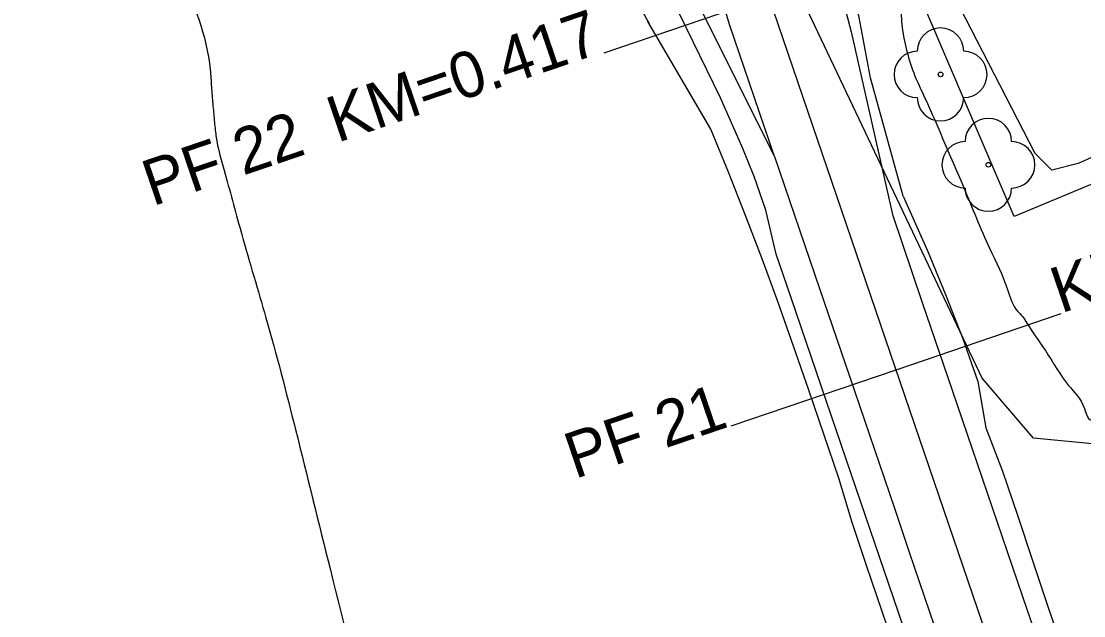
# Model space of a CAD drawing. Extents: x -478102 to -473059, y -1117705 to -1114104.
# Drawn here: x -476531.57 to -476485.84, y -1116863.12 to -1116837.52 of the extents above; entities that cross this region are included whole.
import ezdxf

# ---------------------------------------------------------------- set-up
doc = ezdxf.new("R2010")
doc.units = 0
for name, color, linetype in [('cesty', 7, 'Continuous'), ('ObPÚ', 7, 'Continuous'), ('POLYGONY_SITUACE_PF', 7, 'Continuous'), ('POLYGONY_SITUACE_PF_POPISY', 7, 'Continuous'), ('POLYGONY_SITUACE_PO', 7, 'Continuous'), ('RozhraniKultur', 7, 'Continuous'), ('RozhraniVozovky', 7, 'Continuous'), ('Vrstevnice_hlavni', 7, 'Continuous'), ('Vrstevnice_vedlejsi', 7, 'Continuous'), ('ZnackyStromu', 7, 'Continuous')]:
    doc.layers.add(name, color=color, linetype=linetype)

msp = doc.modelspace()

# ---------------------------------------------------------------- linework, layer by layer
msp.add_line((-476504.565, -1116837.587), (-476505.152, -1116836.498))
msp.add_lwpolyline([(-476493.611, -1116845.046), (-476495.024, -1116839.954), (-476495.915, -1116835.202), (-476496.059, -1116834.438), (-476495.701, -1116828.922), (-476495.475, -1116827.69)])
at = {"layer": 'cesty'}
for p, q in [((-476502.931, -1116835.794), (-476499.157, -1116843.34)), ((-476496.354, -1116836.065), (-476495.859, -1116837.974)), ((-476501.886, -1116842.158), (-476504.604, -1116837.532)), ((-476504.604, -1116837.532), (-476504.565, -1116837.587)), ((-476501.482, -1116840.818), (-476503.246, -1116837.201)), ((-476504.565, -1116837.587), (-476504.553, -1116837.573)), ((-476495.859, -1116837.974), (-476495.859, -1116837.974)), ((-476495.859, -1116837.974), (-476495.859, -1116837.974)), ((-476495.859, -1116837.974), (-476495.859, -1116837.974)), ((-476495.859, -1116837.974), (-476494.08, -1116845.836)), ((-476500.509, -1116843), (-476501.482, -1116840.818)), ((-476501.132, -1116844.013), (-476501.886, -1116842.158)), ((-476500.03, -1116844.197), (-476500.509, -1116843)), ((-476500.402, -1116845.878), (-476501.132, -1116844.013)), ((-476499.527, -1116845.646), (-476500.03, -1116844.197)), ((-476499.076, -1116847.539), (-476499.527, -1116845.646)), ((-476499.69, -1116847.748), (-476500.402, -1116845.878)), ((-476494.08, -1116845.836), (-476492.79, -1116849.622)), ((-476498.43, -1116849.432), (-476499.076, -1116847.539)), ((-476498.997, -1116849.625), (-476499.69, -1116847.748)), ((-476497.785, -1116851.325), (-476498.43, -1116849.432)), ((-476498.334, -1116851.512), (-476498.997, -1116849.625)), ((-476492.79, -1116849.622), (-476491.499, -1116853.408)), ((-476497.68, -1116853.402), (-476498.334, -1116851.512)), ((-476495.849, -1116857.004), (-476497.785, -1116851.325)), ((-476497.031, -1116855.294), (-476497.68, -1116853.402)), ((-476491.499, -1116853.408), (-476490.208, -1116857.194)), ((-476496.382, -1116857.185), (-476497.031, -1116855.294)), ((-476495.805, -1116859.102), (-476496.382, -1116857.185)), ((-476493.268, -1116864.576), (-476495.849, -1116857.004)), ((-476490.208, -1116857.194), (-476489.563, -1116859.087)), ((-476495.173, -1116860.999), (-476495.805, -1116859.102)), ((-476489.563, -1116859.087), (-476488.918, -1116860.98)), ((-476494.532, -1116862.894), (-476495.173, -1116860.999)), ((-476488.918, -1116860.98), (-476488.272, -1116862.873)), ((-476493.891, -1116864.788), (-476494.532, -1116862.894)), ((-476488.272, -1116862.873), (-476487.627, -1116864.766))]:
    msp.add_line(p, q, dxfattribs=at)
for points in [[(-476501.093, -1116837.661), (-476501.723, -1116835.529)], [(-476500.448, -1116839.554), (-476501.093, -1116837.661)], [(-476499.802, -1116841.447), (-476500.448, -1116839.554)], [(-476499.157, -1116843.34), (-476499.802, -1116841.447)], [(-476499.157, -1116843.34), (-476498.512, -1116845.233)], [(-476498.512, -1116845.233), (-476497.866, -1116847.126)], [(-476493.611, -1116845.046), (-476492.549, -1116847.426)], [(-476497.866, -1116847.126), (-476497.221, -1116849.019)], [(-476492.549, -1116847.426), (-476491.797, -1116849.283)], [(-476497.221, -1116849.019), (-476495.93, -1116852.805)], [(-476491.797, -1116849.283), (-476491.061, -1116851.145)], [(-476491.061, -1116851.145), (-476490.394, -1116853.031)], [(-476495.93, -1116852.805), (-476495.285, -1116854.698)], [(-476490.394, -1116853.031), (-476490.058, -1116855.029)], [(-476495.285, -1116854.698), (-476494.64, -1116856.591)], [(-476490.058, -1116855.029), (-476489.332, -1116856.895)], [(-476494.64, -1116856.591), (-476493.994, -1116858.484)], [(-476489.332, -1116856.895), (-476488.696, -1116858.791)], [(-476493.994, -1116858.484), (-476493.349, -1116860.377)], [(-476488.696, -1116858.791), (-476488.061, -1116860.688)], [(-476493.349, -1116860.377), (-476492.704, -1116862.271)], [(-476488.061, -1116860.688), (-476487.426, -1116862.584)], [(-476492.704, -1116862.271), (-476492.058, -1116864.164)], [(-476487.426, -1116862.584), (-476486.79, -1116864.481)]]:
    msp.add_lwpolyline(points, dxfattribs=at)
at = {"layer": 'ObPÚ'}
msp.add_lwpolyline([(-476357.4, -1116837.74), (-476422.93, -1116845.91), (-476427.37, -1116819.37), (-476430.29, -1116820.37), (-476436.91, -1116823.52), (-476455.71, -1116831.67), (-476450.1, -1116844.01), (-476476.04, -1116849.41), (-476482.1, -1116843.09), (-476483.67, -1116843.77), (-476488.84, -1116845.93), (-476490.13, -1116842.91), (-476508.98, -1116798.77)], dxfattribs=at)
at = {"layer": 'POLYGONY_SITUACE_PF'}
for points in [[(-476506.491, -1116838.872), (-476499.392, -1116836.452), (-476492.293, -1116834.032)], [(-476501.013, -1116854.94), (-476493.915, -1116852.52), (-476486.816, -1116850.1)]]:
    msp.add_lwpolyline(points, dxfattribs=at)
at = {"layer": 'POLYGONY_SITUACE_PO'}
msp.add_lwpolyline([(-476301.427, -1117045.065), (-476372.905, -1117052.019), (-476378.974, -1117051.908), (-476382.069, -1117051.436), (-476384.865, -1117050.444), (-476390.281, -1117047.7), (-476394.946, -1117043.817), (-476398.626, -1117038.989), (-476458.957, -1116938.029), (-476465.394, -1116926.586), (-476471.221, -1116914.82), (-476476.422, -1116902.765), (-476480.983, -1116890.454), (-476499.392, -1116836.452), (-476499.929, -1116834.228), (-476500.052, -1116831.944), (-476499.756, -1116829.676), (-476499.052, -1116827.5), (-476496.647, -1116821.88)], dxfattribs=at)
at = {"layer": 'RozhraniKultur'}
for p, q in [((-476488.011, -1116855.464), (-476490.21, -1116852.89)), ((-476485.323, -1116855.734), (-476488.011, -1116855.464))]:
    msp.add_line(p, q, dxfattribs=at)
msp.add_lwpolyline([(-476490.21, -1116852.89), (-476505.97, -1116819.69), (-476509.41, -1116806.69), (-476507.1, -1116784.61)], dxfattribs=at)
at = {"layer": 'RozhraniVozovky'}
msp.add_lwpolyline([(-476490.349, -1116825.506), (-476486.291, -1116834.14), (-476483.076, -1116841.048), (-476483.085, -1116841.925), (-476483.97, -1116842.691), (-476486.077, -1116843.648), (-476487.217, -1116843.934), (-476487.93, -1116843.214), (-476491.436, -1116836.397), (-476497.994, -1116822.204), (-476502.044, -1116811.617), (-476503.151, -1116808.629), (-476503.828, -1116804.26), (-476503.771, -1116799.56), (-476501.723, -1116794.622), (-476498.437, -1116790.602), (-476493.387, -1116786.282), (-476488.978, -1116781.97)], dxfattribs=at)
at = {"layer": 'Vrstevnice_hlavni'}
msp.add_spline([(-476493.715, -1116836.779), (-476493.657, -1116837.782), (-476493.454, -1116838.814), (-476493.106, -1116839.874), (-476492.613, -1116840.964), (-476491.914, -1116842.563), (-476491.008, -1116844.672), (-476489.895, -1116847.291), (-476489.121, -1116849.068), (-476488.687, -1116850.006), (-476488.591, -1116850.102), (-476488.194, -1116850.666), (-476487.494, -1116851.699), (-476486.491, -1116853.199), (-476485.812, -1116854.196), (-476485.456, -1116854.691), (-476485.422, -1116854.683), (-476485.307, -1116854.78), (-476485.109, -1116854.984), (-476484.829, -1116855.293), (-476484.118, -1116857.163), (-476482.975, -1116860.594), (-476481.402, -1116865.585), (-476480.12, -1116869.665), (-476479.13, -1116872.833), (-476478.431, -1116875.088), (-476477.86, -1116876.887), (-476477.416, -1116878.229), (-476477.099, -1116879.115), (-476476.855, -1116880.078), (-476476.685, -1116881.12), (-476476.587, -1116882.239), (-476476.21, -1116884.112), (-476475.555, -1116886.737), (-476474.62, -1116890.115), (-476473.657, -1116893.01), (-476472.666, -1116895.422), (-476471.647, -1116897.352), (-476470.243, -1116900.412), (-476468.455, -1116904.603), (-476466.283, -1116909.925), (-476464.77, -1116913.634), (-476463.916, -1116915.731), (-476463.721, -1116916.214), (-476463.617, -1116916.722), (-476463.603, -1116917.256), (-476463.679, -1116917.815), (-476463.509, -1116918.911), (-476463.093, -1116920.547), (-476462.43, -1116922.72), (-476462.028, -1116926.548), (-476461.886, -1116932.03), (-476462.123, -1116946.304)], degree=3, dxfattribs=at)
at = {"layer": 'Vrstevnice_vedlejsi'}
msp.add_spline([(-476571.958, -1116704.162), (-476571.904, -1116704.215), (-476571.688, -1116704.429), (-476571.311, -1116704.803), (-476570.773, -1116705.338), (-476569.946, -1116706.363), (-476568.83, -1116707.879), (-476567.427, -1116709.886), (-476566.203, -1116711.628), (-476565.16, -1116713.105), (-476564.298, -1116714.317), (-476563.772, -1116715.225), (-476563.581, -1116715.829), (-476563.726, -1116716.129), (-476564.073, -1116716.669), (-476564.621, -1116717.45), (-476565.371, -1116718.471), (-476565.697, -1116719.715), (-476565.599, -1116721.18), (-476565.077, -1116722.867), (-476563.322, -1116725.926), (-476560.334, -1116730.356), (-476556.114, -1116736.158), (-476552.562, -1116741.631), (-476549.677, -1116746.776), (-476547.46, -1116751.593), (-476545.693, -1116756.042), (-476544.374, -1116760.122), (-476543.504, -1116763.833), (-476542.206, -1116769.314), (-476540.482, -1116776.566), (-476538.329, -1116785.587), (-476536.736, -1116792.746), (-476535.702, -1116798.044), (-476535.228, -1116801.481), (-476533.66, -1116807.541), (-476530.999, -1116816.224), (-476527.246, -1116827.53), (-476524.726, -1116835.32), (-476523.44, -1116839.595), (-476523.389, -1116840.354), (-476523.331, -1116841.083), (-476523.266, -1116841.783), (-476523.195, -1116842.453), (-476522.8, -1116844.094), (-476522.082, -1116846.705), (-476521.041, -1116850.288), (-476519.77, -1116855.097), (-476518.27, -1116861.134), (-476516.539, -1116868.399), (-476515.387, -1116873.283), (-476514.813, -1116875.785), (-476514.818, -1116875.907), (-476514.695, -1116876.43), (-476514.444, -1116877.353), (-476514.064, -1116878.676), (-476513.598, -1116880.016), (-476513.045, -1116881.373), (-476512.404, -1116882.746), (-476510.965, -1116886.684), (-476508.726, -1116893.188), (-476505.69, -1116902.257), (-476503.32, -1116909.062), (-476501.617, -1116913.604), (-476500.581, -1116915.881), (-476499.982, -1116918.695), (-476499.82, -1116922.044), (-476500.095, -1116925.93), (-476500.622, -1116930.955), (-476501.399, -1116937.119), (-476502.428, -1116944.424), (-476503.284, -1116951.043), (-476503.968, -1116956.977), (-476504.479, -1116962.226), (-476505.481, -1116968.833), (-476506.974, -1116976.798), (-476508.959, -1116986.121), (-476510.49, -1116993.241), (-476511.568, -1116998.159), (-476512.192, -1117000.873), (-476513.406, -1117005.693), (-476515.21, -1117012.619), (-476517.605, -1117021.651), (-476519.543, -1117028.708), (-476521.025, -1117033.789), (-476522.05, -1117036.895), (-476522.813, -1117039.387), (-476523.316, -1117041.266), (-476523.557, -1117042.532), (-476525.061, -1117047.398), (-476527.83, -1117055.865), (-476531.861, -1117067.933), (-476534.429, -1117077.623), (-476535.532, -1117084.937), (-476535.172, -1117089.874), (-476535.368, -1117095.964), (-476536.121, -1117103.207)], degree=3, dxfattribs=at)
at = {"layer": 'ZnackyStromu'}
for centre in [(-476492.005, -1116839.806), (-476489.947, -1116843.697)]:
    msp.add_circle(centre, 0.1, dxfattribs=at)
for centre, start, end in [((-476492.005, -1116838.806), 0, 180), ((-476493.005, -1116839.806), 90, 270), ((-476491.005, -1116839.806), 270, 90), ((-476492.005, -1116840.806), 180, 0), ((-476489.947, -1116842.697), 0, 180), ((-476490.947, -1116843.697), 90, 270), ((-476488.947, -1116843.697), 270, 90), ((-476489.947, -1116844.697), 180, 0)]:
    msp.add_arc(centre, 1, start, end, dxfattribs=at)

# ---------------------------------------------------------------- texts
at = {"layer": 'POLYGONY_SITUACE_PF_POPISY'}
for s, p in [('KM=0.417', (-476517.972, -1116842.754)), ('PF 22', (-476525.924, -1116845.493)), ('KM=0.400', (-476486.827, -1116850.104)), ('PF 21', (-476507.748, -1116857.236))]:
    msp.add_text(s, height=1.9765, rotation=18.8241, dxfattribs=at).set_placement(p)

doc.saveas('drawing.dxf')
